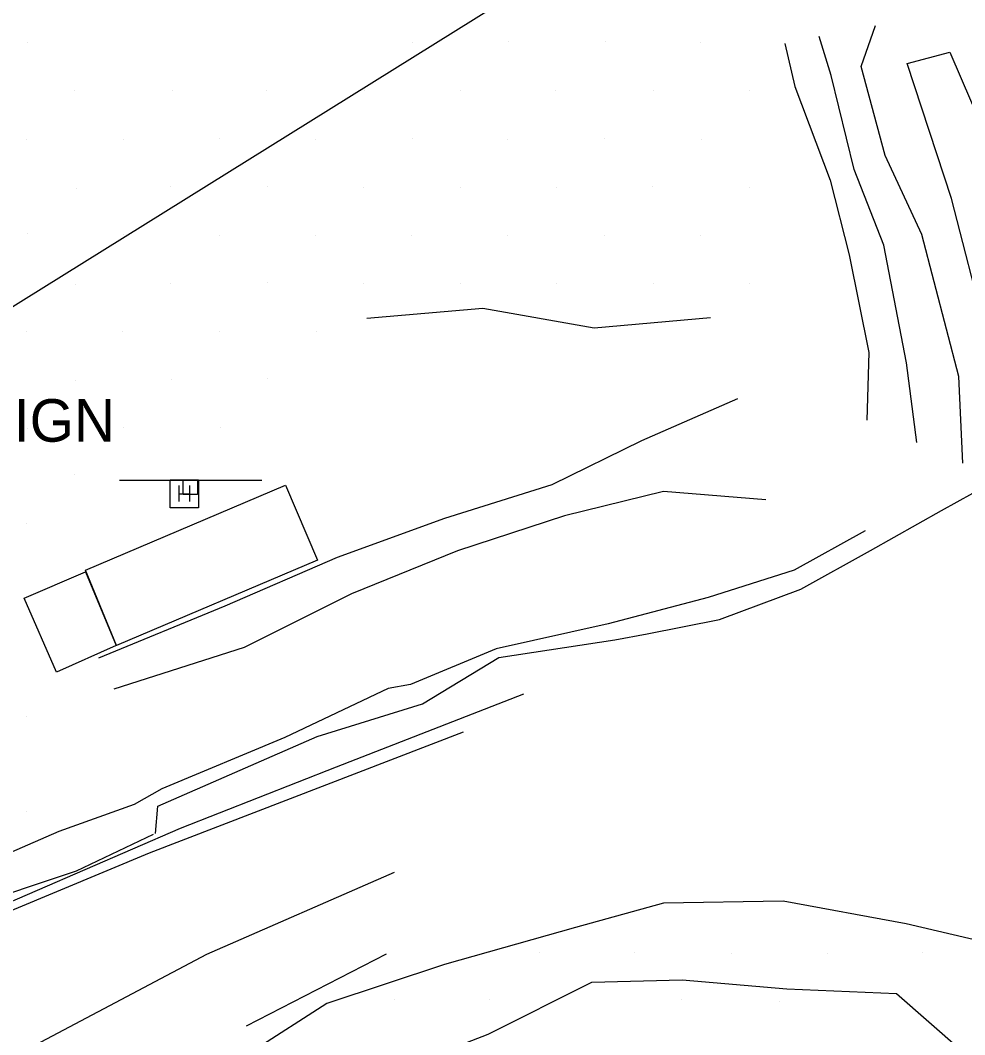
# Model space of a CAD drawing. Extents: x 1602514 to 1609837, y 863887 to 871157.
# Drawn here: x 1605274 to 1605412.7, y 867620.1 to 867769.2 of the extents above; entities that cross this region are included whole.
import ezdxf

# ---------------------------------------------------------------- set-up
doc = ezdxf.new("R2010")
doc.units = 0
for name, color, linetype in [('Roadway-Signs', 7, 'Continuous'), ('Survey-Buildings', 7, 'Continuous'), ('Survey-Centerline', 7, 'Continuous'), ('Survey-Edge of pavement', 7, 'Continuous'), ('Survey-Entrances', 7, 'Continuous'), ('Survey-Flow line', 7, 'Continuous'), ('Survey-Misc paved surface', 7, 'Continuous'), ('Survey-Ridge Lines', 7, 'Continuous'), ('Survey-Safety', 7, 'Continuous'), ('Survey-Shoulders', 7, 'Continuous'), ('Survey-Spot dirt', 7, 'Continuous'), ('Survey-Vegetation trees', 7, 'Continuous'), ('USER-Handhole', 7, 'Continuous')]:
    doc.layers.add(name, color=color, linetype=linetype)

msp = doc.modelspace()

# ---------------------------------------------------------------- linework, layer by layer
at = {"layer": 'Roadway-Signs'}
for p, q in [((1605288.59, 867701.59), (1605309.49, 867701.59)), ((1605288.59, 867701.59), (1605309.49, 867701.59)), ((1605297.94, 867699.49), (1605297.94, 867701.59)), ((1605297.94, 867699.49), (1605297.94, 867701.59)), ((1605298.99, 867701.59), (1605298.99, 867701.59)), ((1605298.99, 867701.59), (1605298.99, 867701.59)), ((1605300.04, 867701.59), (1605300.04, 867699.49)), ((1605300.04, 867701.59), (1605300.04, 867699.49)), ((1605300.04, 867699.49), (1605297.94, 867699.49)), ((1605300.04, 867699.49), (1605297.94, 867699.49))]:
    msp.add_line(p, q, dxfattribs=at)
at = {"layer": 'Survey-Buildings'}
msp.add_lwpolyline([(1605283.61, 867688.36), (1605312.99, 867700.87), (1605317.67, 867689.82), (1605288.14, 867677.29)], close=True, dxfattribs=at)
msp.add_lwpolyline([(1605283.61, 867688.36), (1605312.99, 867700.87), (1605317.67, 867689.82), (1605288.14, 867677.29)], close=True, dxfattribs=at)
at = {"layer": 'Survey-Centerline'}
msp.add_lwpolyline([(1605328.92, 867643.96), (1605301.38, 867631.92), (1605259.31, 867609.66), (1605246.25, 867602.76)], dxfattribs=at)
msp.add_lwpolyline([(1605328.92, 867643.96), (1605301.38, 867631.92), (1605259.31, 867609.66), (1605246.25, 867602.76)], dxfattribs=at)
at = {"layer": 'Survey-Edge of pavement'}
for p, q in [((1605293.02, 867646.84), (1605339.11, 867664.6)), ((1605293.02, 867646.84), (1605339.11, 867664.6)), ((1605307.26, 867621.41), (1605327.82, 867631.99)), ((1605307.26, 867621.41), (1605327.82, 867631.99))]:
    msp.add_line(p, q, dxfattribs=at)
at = {"layer": 'Survey-Entrances'}
for points in [[(1605414.54, 867701.25), (1605418.36, 867709.05), (1605415.84, 867723.36), (1605410.8, 867742.95), (1605404.3, 867762.78), (1605410.56, 867764.49), (1605418.27, 867746.52), (1605421.93, 867731.24), (1605427.29, 867710.51), (1605427.86, 867705.39)], [(1605414.54, 867701.25), (1605418.36, 867709.05), (1605415.84, 867723.36), (1605410.8, 867742.95), (1605404.3, 867762.78), (1605410.56, 867764.49), (1605418.27, 867746.52), (1605421.93, 867731.24), (1605427.29, 867710.51), (1605427.86, 867705.39)], [(1605266.34, 867635.73), (1605293.02, 867646.84)], [(1605266.34, 867635.73), (1605293.02, 867646.84)]]:
    msp.add_lwpolyline(points, dxfattribs=at)
at = {"layer": 'Survey-Flow line'}
msp.add_lwpolyline([(1605405.71, 867707.11), (1605404.2, 867718.85), (1605400.85, 867736.13), (1605396.47, 867747.23), (1605393.13, 867761.02), (1605391.37, 867766.75)], dxfattribs=at)
msp.add_lwpolyline([(1605405.71, 867707.11), (1605404.2, 867718.85), (1605400.85, 867736.13), (1605396.47, 867747.23), (1605393.13, 867761.02), (1605391.37, 867766.75)], dxfattribs=at)
at = {"layer": 'Survey-Misc paved surface'}
msp.add_lwpolyline([(1605283.61, 867688.1), (1605288.09, 867677.29), (1605279.33, 867673.39), (1605274.59, 867684.25)], close=True, dxfattribs=at)
msp.add_lwpolyline([(1605283.61, 867688.1), (1605288.09, 867677.29), (1605279.33, 867673.39), (1605274.59, 867684.25)], close=True, dxfattribs=at)
at = {"layer": 'Survey-Ridge Lines'}
for points in [[(1605412.46, 867704.08), (1605411.86, 867716.81), (1605406.41, 867737.69), (1605401.07, 867749.28), (1605397.53, 867762.35), (1605399.62, 867768.4)], [(1605412.46, 867704.08), (1605411.86, 867716.81), (1605406.41, 867737.69), (1605401.07, 867749.28), (1605397.53, 867762.35), (1605399.62, 867768.4)], [(1605386.31, 867765.74), (1605387.77, 867759.41), (1605392.97, 867745.67), (1605395.78, 867734.71), (1605398.66, 867720.33), (1605398.36, 867710.41)], [(1605386.31, 867765.74), (1605387.77, 867759.41), (1605392.97, 867745.67), (1605395.78, 867734.71), (1605398.66, 867720.33), (1605398.36, 867710.41)], [(1605375.41, 867725.44), (1605358.32, 867723.9), (1605341.94, 867726.8), (1605324.92, 867725.33)], [(1605375.41, 867725.44), (1605358.32, 867723.9), (1605341.94, 867726.8), (1605324.92, 867725.33)], [(1605285.57, 867675.48), (1605304.11, 867683.15), (1605320.59, 867690.3), (1605336.37, 867696.01), (1605352.15, 867700.96), (1605365.31, 867707.41), (1605379.39, 867713.57)], [(1605285.57, 867675.48), (1605304.11, 867683.15), (1605320.59, 867690.3), (1605336.37, 867696.01), (1605352.15, 867700.96), (1605365.31, 867707.41), (1605379.39, 867713.57)], [(1605383.51, 867698.69), (1605368.49, 867699.92), (1605353.97, 867696.36), (1605338.25, 867691.19), (1605322.67, 867684.89), (1605306.89, 867677.02), (1605287.78, 867670.88)], [(1605383.51, 867698.69), (1605368.49, 867699.92), (1605353.97, 867696.36), (1605338.25, 867691.19), (1605322.67, 867684.89), (1605306.89, 867677.02), (1605287.78, 867670.88)], [(1605398.09, 867694.13), (1605387.66, 867688.38), (1605375.05, 867684.34), (1605360.38, 867680.5), (1605343.89, 867676.8), (1605331.32, 867671.55), (1605328.05, 867670.96), (1605312.89, 867663.8), (1605294.8, 867656.22), (1605290.75, 867653.95), (1605279.67, 867649.95), (1605264.25, 867643.28), (1605258.03, 867643.19)], [(1605398.09, 867694.13), (1605387.66, 867688.38), (1605375.05, 867684.34), (1605360.38, 867680.5), (1605343.89, 867676.8), (1605331.32, 867671.55), (1605328.05, 867670.96), (1605312.89, 867663.8), (1605294.8, 867656.22), (1605290.75, 867653.95), (1605279.67, 867649.95), (1605264.25, 867643.28), (1605258.03, 867643.19)], [(1605603.96, 867440.07), (1605583.83, 867460.37), (1605565.35, 867486.57), (1605553.38, 867500.64), (1605541.95, 867516.46), (1605526.55, 867535.29), (1605517.42, 867546.63), (1605502, 867558.9), (1605492.51, 867573.2), (1605482.75, 867585.47), (1605470.16, 867596.8), (1605454.46, 867609.33), (1605437.55, 867620.66), (1605425.71, 867626.54), (1605415.65, 867633.7), (1605404.14, 867636.4), (1605386.08, 867639.73), (1605368.47, 867639.47), (1605355.56, 867635.89), (1605336.33, 867630.44), (1605319.04, 867624.72), (1605297.39, 867610.81), (1605287.37, 867594.77), (1605287.44, 867578.17)], [(1605603.96, 867440.07), (1605583.83, 867460.37), (1605565.35, 867486.57), (1605553.38, 867500.64), (1605541.95, 867516.46), (1605526.55, 867535.29), (1605517.42, 867546.63), (1605502, 867558.9), (1605492.51, 867573.2), (1605482.75, 867585.47), (1605470.16, 867596.8), (1605454.46, 867609.33), (1605437.55, 867620.66), (1605425.71, 867626.54), (1605415.65, 867633.7), (1605404.14, 867636.4), (1605386.08, 867639.73), (1605368.47, 867639.47), (1605355.56, 867635.89), (1605336.33, 867630.44), (1605319.04, 867624.72), (1605297.39, 867610.81), (1605287.37, 867594.77), (1605287.44, 867578.17)], [(1605327.09, 867614.12), (1605342.74, 867620.19), (1605357.98, 867627.86), (1605371.22, 867628.2), (1605386.61, 867626.86), (1605402.72, 867626.17), (1605412.2, 867617.87)], [(1605327.09, 867614.12), (1605342.74, 867620.19), (1605357.98, 867627.86), (1605371.22, 867628.2), (1605386.61, 867626.86), (1605402.72, 867626.17), (1605412.2, 867617.87)]]:
    msp.add_lwpolyline(points, dxfattribs=at)
at = {"layer": 'Survey-Safety'}
msp.add_lwpolyline([(1605269.5, 867638.32), (1605297.57, 867650.45), (1605320.48, 867659.48), (1605348, 867670.2)], dxfattribs=at)
msp.add_lwpolyline([(1605269.5, 867638.32), (1605297.57, 867650.45), (1605320.48, 867659.48), (1605348, 867670.2)], dxfattribs=at)
at = {"layer": 'Survey-Shoulders'}
for points in [[(1605293.54, 867649.54), (1605282.21, 867644.13), (1605265.91, 867638.69), (1605259.07, 867636.83), (1605254.43, 867636.59), (1605245.05, 867636.2), (1605233.77, 867642.69), (1605228.41, 867649.44), (1605216.41, 867666.82), (1605205.63, 867682.19), (1605193.95, 867698.43), (1605181.33, 867718.65), (1605174.37, 867728.2), (1605161.95, 867744.77), (1605153.56, 867755.46)], [(1605293.54, 867649.54), (1605282.21, 867644.13), (1605265.91, 867638.69), (1605259.07, 867636.83), (1605254.43, 867636.59), (1605245.05, 867636.2), (1605233.77, 867642.69), (1605228.41, 867649.44), (1605216.41, 867666.82), (1605205.63, 867682.19), (1605193.95, 867698.43), (1605181.33, 867718.65), (1605174.37, 867728.2), (1605161.95, 867744.77), (1605153.56, 867755.46)], [(1605293.9, 867649.69), (1605294.24, 867653.68), (1605317.62, 867663.92), (1605333.08, 867668.75), (1605344.3, 867675.52), (1605361.33, 867678.13), (1605366.1, 867678.99), (1605376.71, 867681.12), (1605388.67, 867685.57), (1605398.89, 867691.25), (1605409.33, 867697.12), (1605416.23, 867700.94), (1605426.54, 867704.84), (1605430.61, 867697.77), (1605434.75, 867690.75), (1605440.19, 867683.71), (1605443.91, 867678.27), (1605447.83, 867671.83), (1605451.91, 867663.43), (1605456.89, 867657.91), (1605467.25, 867644.5), (1605477.54, 867633.16)], [(1605293.9, 867649.69), (1605294.24, 867653.68), (1605317.62, 867663.92), (1605333.08, 867668.75), (1605344.3, 867675.52), (1605361.33, 867678.13), (1605366.1, 867678.99), (1605376.71, 867681.12), (1605388.67, 867685.57), (1605398.89, 867691.25), (1605409.33, 867697.12), (1605416.23, 867700.94), (1605426.54, 867704.84), (1605430.61, 867697.77), (1605434.75, 867690.75), (1605440.19, 867683.71), (1605443.91, 867678.27), (1605447.83, 867671.83), (1605451.91, 867663.43), (1605456.89, 867657.91), (1605467.25, 867644.5), (1605477.54, 867633.16)]]:
    msp.add_lwpolyline(points, dxfattribs=at)
at = {"layer": 'Survey-Spot dirt'}
for p, q in [((1605275.05, 867765.89), (1605275.05, 867765.89)), ((1605275.05, 867765.89), (1605275.05, 867765.89)), ((1605331.67, 867765.9), (1605331.67, 867765.9)), ((1605331.67, 867765.9), (1605331.67, 867765.9)), ((1605345.79, 867765.98), (1605345.79, 867765.98)), ((1605345.79, 867765.98), (1605345.79, 867765.98)), ((1605359.92, 867765.98), (1605359.92, 867765.98)), ((1605359.92, 867765.98), (1605359.92, 867765.98)), ((1605373.99, 867765.86), (1605373.99, 867765.86)), ((1605373.99, 867765.86), (1605373.99, 867765.86)), ((1605281.96, 867758.81), (1605281.96, 867758.81)), ((1605281.96, 867758.81), (1605281.96, 867758.81)), ((1605296.45, 867758.88), (1605296.45, 867758.88)), ((1605296.45, 867758.88), (1605296.45, 867758.88)), ((1605310.24, 867758.83), (1605310.24, 867758.83)), ((1605310.24, 867758.83), (1605310.24, 867758.83)), ((1605324.54, 867758.85), (1605324.54, 867758.85)), ((1605324.54, 867758.85), (1605324.54, 867758.85)), ((1605338.65, 867758.77), (1605338.65, 867758.77)), ((1605338.65, 867758.77), (1605338.65, 867758.77)), ((1605352.69, 867758.82), (1605352.69, 867758.82)), ((1605352.69, 867758.82), (1605352.69, 867758.82)), ((1605367, 867758.78), (1605367, 867758.78)), ((1605367, 867758.78), (1605367, 867758.78)), ((1605381.07, 867758.81), (1605381.07, 867758.81)), ((1605381.07, 867758.81), (1605381.07, 867758.81)), ((1605274.98, 867751.71), (1605274.98, 867751.71)), ((1605274.98, 867751.71), (1605274.98, 867751.71)), ((1605289.19, 867751.71), (1605289.19, 867751.71)), ((1605289.19, 867751.71), (1605289.19, 867751.71)), ((1605303.25, 867751.73), (1605303.25, 867751.73)), ((1605303.25, 867751.73), (1605303.25, 867751.73)), ((1605317.35, 867751.61), (1605317.35, 867751.61)), ((1605317.35, 867751.61), (1605317.35, 867751.61)), ((1605331.61, 867751.76), (1605331.61, 867751.76)), ((1605331.61, 867751.76), (1605331.61, 867751.76)), ((1605345.64, 867751.71), (1605345.64, 867751.71)), ((1605345.64, 867751.71), (1605345.64, 867751.71)), ((1605359.8, 867751.82), (1605359.8, 867751.82)), ((1605359.8, 867751.82), (1605359.8, 867751.82)), ((1605374.02, 867751.68), (1605374.02, 867751.68)), ((1605374.02, 867751.68), (1605374.02, 867751.68)), ((1605296.08, 867744.73), (1605296.08, 867744.73)), ((1605296.08, 867744.73), (1605296.08, 867744.73)), ((1605310.27, 867744.67), (1605310.27, 867744.67)), ((1605310.27, 867744.67), (1605310.27, 867744.67)), ((1605366.82, 867744.8), (1605366.82, 867744.8)), ((1605366.82, 867744.8), (1605366.82, 867744.8)), ((1605381.05, 867744.65), (1605381.05, 867744.65)), ((1605381.05, 867744.65), (1605381.05, 867744.65)), ((1605282.26, 867744.39), (1605282.26, 867744.39)), ((1605282.26, 867744.39), (1605282.26, 867744.39)), ((1605324.47, 867744.61), (1605324.47, 867744.61)), ((1605324.47, 867744.61), (1605324.47, 867744.61)), ((1605338.66, 867744.62), (1605338.66, 867744.62)), ((1605338.66, 867744.62), (1605338.66, 867744.62)), ((1605352.74, 867744.62), (1605352.74, 867744.62)), ((1605352.74, 867744.62), (1605352.74, 867744.62)), ((1605275.05, 867737.78), (1605275.05, 867737.78)), ((1605275.05, 867737.78), (1605275.05, 867737.78)), ((1605289.15, 867737.61), (1605289.15, 867737.61)), ((1605289.15, 867737.61), (1605289.15, 867737.61)), ((1605303.24, 867737.5), (1605303.24, 867737.5)), ((1605303.24, 867737.5), (1605303.24, 867737.5)), ((1605317.41, 867737.56), (1605317.41, 867737.56)), ((1605317.41, 867737.56), (1605317.41, 867737.56)), ((1605331.48, 867737.55), (1605331.48, 867737.55)), ((1605331.48, 867737.55), (1605331.48, 867737.55)), ((1605345.63, 867737.5), (1605345.63, 867737.5)), ((1605345.63, 867737.5), (1605345.63, 867737.5)), ((1605359.82, 867737.59), (1605359.82, 867737.59)), ((1605359.82, 867737.59), (1605359.82, 867737.59)), ((1605373.96, 867737.57), (1605373.96, 867737.57)), ((1605373.96, 867737.57), (1605373.96, 867737.57)), ((1605282.13, 867730.39), (1605282.13, 867730.39)), ((1605282.13, 867730.39), (1605282.13, 867730.39)), ((1605296.15, 867730.49), (1605296.15, 867730.49)), ((1605296.15, 867730.49), (1605296.15, 867730.49)), ((1605310.3, 867730.69), (1605310.3, 867730.69)), ((1605310.3, 867730.69), (1605310.3, 867730.69)), ((1605324.45, 867730.55), (1605324.45, 867730.55)), ((1605324.45, 867730.55), (1605324.45, 867730.55)), ((1605338.64, 867730.41), (1605338.64, 867730.41)), ((1605338.64, 867730.41), (1605338.64, 867730.41)), ((1605352.83, 867730.49), (1605352.83, 867730.49)), ((1605352.83, 867730.49), (1605352.83, 867730.49)), ((1605367.01, 867730.46), (1605367.01, 867730.46)), ((1605367.01, 867730.46), (1605367.01, 867730.46)), ((1605381.06, 867730.49), (1605381.06, 867730.49)), ((1605381.06, 867730.49), (1605381.06, 867730.49)), ((1605274.92, 867723.49), (1605274.92, 867723.49)), ((1605274.92, 867723.49), (1605274.92, 867723.49)), ((1605289.06, 867723.44), (1605289.06, 867723.44)), ((1605289.06, 867723.44), (1605289.06, 867723.44)), ((1605303.23, 867723.5), (1605303.23, 867723.5)), ((1605303.23, 867723.5), (1605303.23, 867723.5)), ((1605317.55, 867723.36), (1605317.55, 867723.36)), ((1605317.55, 867723.36), (1605317.55, 867723.36)), ((1605296.17, 867716.37), (1605296.17, 867716.37)), ((1605296.17, 867716.37), (1605296.17, 867716.37)), ((1605310.27, 867716.49), (1605310.27, 867716.49)), ((1605310.27, 867716.49), (1605310.27, 867716.49)), ((1605282.09, 867716.29), (1605282.09, 867716.29)), ((1605282.09, 867716.29), (1605282.09, 867716.29)), ((1605275.07, 867709.17), (1605275.07, 867709.17)), ((1605275.07, 867709.17), (1605275.07, 867709.17)), ((1605289.18, 867709.26), (1605289.18, 867709.26)), ((1605289.18, 867709.26), (1605289.18, 867709.26)), ((1605303.41, 867709.28), (1605303.41, 867709.28)), ((1605303.41, 867709.28), (1605303.41, 867709.28)), ((1605281.99, 867702.46), (1605281.99, 867702.46)), ((1605281.99, 867702.46), (1605281.99, 867702.46)), ((1605274.96, 867695.24), (1605274.96, 867695.24)), ((1605274.96, 867695.24), (1605274.96, 867695.24)), ((1605274.96, 867666.88), (1605274.96, 867666.88)), ((1605274.96, 867666.88), (1605274.96, 867666.88)), ((1605274.88, 867652.86), (1605274.88, 867652.86)), ((1605274.88, 867652.86), (1605274.88, 867652.86)), ((1605350.25, 867632.18), (1605350.25, 867632.18)), ((1605350.25, 867632.18), (1605350.25, 867632.18)), ((1605364.24, 867632.23), (1605364.24, 867632.23)), ((1605364.24, 867632.23), (1605364.24, 867632.23)), ((1605378.52, 867631.98), (1605378.52, 867631.98)), ((1605378.52, 867631.98), (1605378.52, 867631.98)), ((1605392.56, 867632.12), (1605392.56, 867632.12)), ((1605392.56, 867632.12), (1605392.56, 867632.12)), ((1605406.49, 867632.27), (1605406.49, 867632.27)), ((1605406.49, 867632.27), (1605406.49, 867632.27)), ((1605328.91, 867625.33), (1605328.91, 867625.33)), ((1605328.91, 867625.33), (1605328.91, 867625.33)), ((1605342.91, 867625.31), (1605342.91, 867625.31)), ((1605342.91, 867625.31), (1605342.91, 867625.31)), ((1605371.19, 867625.26), (1605371.19, 867625.26)), ((1605371.19, 867625.26), (1605371.19, 867625.26)), ((1605385.52, 867625.07), (1605385.52, 867625.07)), ((1605385.52, 867625.07), (1605385.52, 867625.07))]:
    msp.add_line(p, q, dxfattribs=at)
at = {"layer": 'Survey-Vegetation trees'}
msp.add_lwpolyline([(1604526.23, 869070.02), (1604587.99, 868903.85), (1604648.37, 868745.93), (1604701.9, 868632.63), (1604712.19, 868619.59), (1604746.5, 868500.11), (1604748.56, 868452.05), (1604792.9, 868384.62), (1604842.07, 868297.14), (1604881.2, 868202.42), (1604962.8, 868058.28), (1605037.44, 867955.22), (1605112.82, 867870.34), (1605164.26, 867779.29), (1605243.81, 867709), (1605352.92, 867776.98), (1605409.19, 867794.14), (1605453.11, 867683.59), (1605568.4, 867553.13), (1605652.11, 867437.78), (1605709.38, 867356.87), (1605792.64, 867252.16), (1605890.79, 867280.68)], dxfattribs=at)
msp.add_lwpolyline([(1604526.23, 869070.02), (1604587.99, 868903.85), (1604648.37, 868745.93), (1604701.9, 868632.63), (1604712.19, 868619.59), (1604746.5, 868500.11), (1604748.56, 868452.05), (1604792.9, 868384.62), (1604842.07, 868297.14), (1604881.2, 868202.42), (1604962.8, 868058.28), (1605037.44, 867955.22), (1605112.82, 867870.34), (1605164.26, 867779.29), (1605243.81, 867709), (1605352.92, 867776.98), (1605409.19, 867794.14), (1605453.11, 867683.59), (1605568.4, 867553.13), (1605652.11, 867437.78), (1605709.38, 867356.87), (1605792.64, 867252.16), (1605890.79, 867280.68)], dxfattribs=at)
at = {"layer": 'USER-Handhole'}
for p, q in [((1605296.05, 867701.66), (1605300.18, 867701.66)), ((1605296.05, 867697.52), (1605296.05, 867701.66)), ((1605296.05, 867701.66), (1605300.18, 867701.66)), ((1605296.05, 867697.52), (1605296.05, 867701.66)), ((1605300.18, 867701.66), (1605300.18, 867697.52)), ((1605300.18, 867701.66), (1605300.18, 867697.52)), ((1605297.33, 867700.83), (1605297.33, 867698.44)), ((1605297.33, 867700.83), (1605297.33, 867698.44)), ((1605298.89, 867700.83), (1605298.89, 867698.44)), ((1605298.89, 867700.83), (1605298.89, 867698.44)), ((1605297.33, 867699.59), (1605298.89, 867699.59)), ((1605297.33, 867699.59), (1605298.89, 867699.59)), ((1605300.18, 867697.52), (1605296.05, 867697.52)), ((1605300.18, 867697.52), (1605296.05, 867697.52))]:
    msp.add_line(p, q, dxfattribs=at)

# ---------------------------------------------------------------- texts
at = {"layer": 'Roadway-Signs'}
msp.add_text('SIGN', height=6.25, dxfattribs=at).set_placement((1605267.51, 867707.24))
msp.add_text('SIGN', height=6.25, dxfattribs=at).set_placement((1605267.51, 867707.24))

doc.saveas('drawing.dxf')
